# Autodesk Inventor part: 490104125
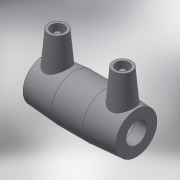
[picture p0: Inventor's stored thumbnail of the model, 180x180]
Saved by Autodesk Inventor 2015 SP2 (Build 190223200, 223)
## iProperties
Created: 2017-06
Part Number: 490104125
Material: Generic
Description: PLASSON COUPLER 125-125
Document SubType Name: Modeling
Designer: KIM
Mass: 55.0731 g
Surface Area: 148.067 cm^2
Volume: 55.0731 cm^3
Density: 1 g/cm^3
Appearance: Default
Author: KIM
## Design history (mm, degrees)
derived "490104.ipt"
feature "Solid1::490104.ipt"
tag "TaggingFeature1"
body "Solid1"
other parameters: "d0" = 173, "d1" = 125, "d2" = 157, "d3" = 85, "d4" = 57.66667, "d5" = 141.3, "d6" = 118.75, "d7" = 125, "d8" = 168 deg, "d10" = 34, "d11" = 11.33333, "d13" = 173, "d14" = 17.6296, "d15" = 85, "d16" = 85, "d17" = 118.75, "d18" = 125, "d19" = 3.52592, "d20" = 168 deg, "d22" = 147.58, "d23" = 157, "d24" = 143.1526, "d25" = 135 deg, "d26" = 69.2, "d27" = 135 deg, "d29" = 87, "d30" = 14, "d31" = 60.55, "d34" = 5 deg, "d35" = 15, "d39" = 5 deg, "d41" = 4, "d42" = 14, "d43" = 0, "d45" = 4, "d46" = 14, "d47" = 0, "d48" = 3, "d49" = 0, "d50" = 3, "d51" = 0, "d52" = 24.65, "d53" = 6.1625, "d_" = 125, "L_" = 173, "L_1" = 85, "D_" = 157, "A_" = 87, "d_2" = 12
